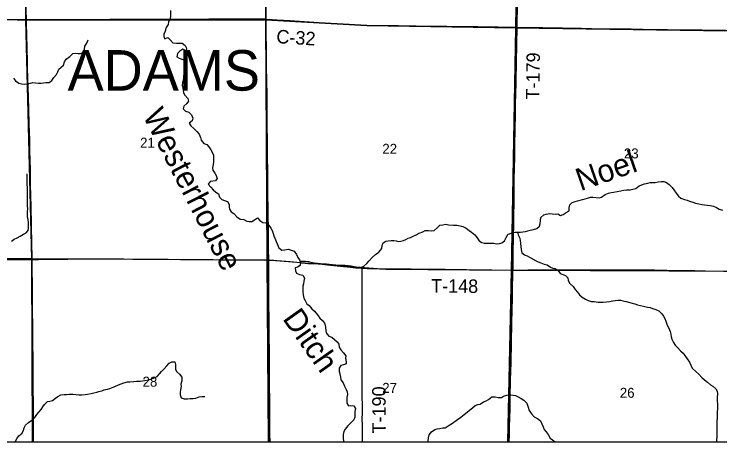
# Model space of a CAD drawing. Extents: x -8.5 to 18.7, y -20.3 to 7.
# Drawn here: x 3.11 to 9.06, y -20.26 to -16.66 of the extents above; entities that cross this region are included whole.
import ezdxf

# ---------------------------------------------------------------- set-up
doc = ezdxf.new("R2010")
doc.units = 0
for name, color, linetype in [('GM_X_Corporation', 7, 'Continuous'), ('GM_X_County_Road', 7, 'Continuous'), ('GM_X_County_Road_Text', 7, 'Continuous'), ('GM_X_Minor_River', 7, 'Continuous'), ('GM_X_Minor_River_Text', 7, 'Continuous'), ('GM_X_Section', 7, 'Continuous'), ('GM_X_Section_Text', 7, 'Continuous'), ('GM_X_State_Route', 7, 'Continuous'), ('GM_X_Township_Road', 7, 'Continuous'), ('GM_X_Township_Road_Text', 7, 'Continuous'), ('GM_X_Township_Text', 7, 'Continuous'), ('GM_X_Unincorporated_Text', 7, 'Continuous'), ('SH_Cut_Line', 7, 'Continuous')]:
    doc.layers.add(name, color=color, linetype=linetype)

msp = doc.modelspace()

# ---------------------------------------------------------------- linework, layer by layer
at = {"layer": 'GM_X_Corporation'}
msp.add_lwpolyline([(-0.9232, -20.262), (11.2623, -20.262)], dxfattribs=at)
at = {"layer": 'GM_X_County_Road'}
for points in [[(5.231, -16.7039), (5.2834, -16.707), (5.3255, -16.7098), (5.4323, -16.7162), (5.6768, -16.7311), (5.848, -16.7419), (6.028, -16.7528), (6.0764, -16.7545), (6.1671, -16.7562), (6.3486, -16.7583), (6.4966, -16.7597), (6.6271, -16.7616), (6.6744, -16.7619), (6.7564, -16.7633), (6.831, -16.7641), (6.9131, -16.7652), (7.0175, -16.7666), (7.0958, -16.7671), (7.1866, -16.7683), (7.3346, -16.7708), (7.3471, -16.771)], [(7.3471, -16.771), (7.5621, -16.7748), (7.6354, -16.7759), (7.7299, -16.7774), (7.7908, -16.7785), (7.8902, -16.7802), (7.9735, -16.7818), (8.1998, -16.7851), (8.3067, -16.7862), (8.5131, -16.7898), (8.5566, -16.7903), (8.615, -16.7911), (8.7393, -16.7925), (8.8102, -16.7933), (8.9072, -16.7947), (9.0154, -16.7963), (9.1024, -16.7972), (9.264, -16.7988), (9.3137, -16.7991), (9.3259, -16.7991)]]:
    msp.add_lwpolyline(points, dxfattribs=at)
at = {"layer": 'GM_X_Minor_River'}
for points in [[(4.4271, -16.6294), (4.4283, -16.681), (4.4206, -16.7067), (4.4114, -16.7272), (4.4067, -16.7476), (4.3907, -16.7748), (4.3807, -16.8036), (4.3715, -16.8293), (4.3698, -16.8483), (4.378, -16.8681), (4.4038, -16.8576), (4.4241, -16.8789), (4.4474, -16.9033), (4.4762, -16.9058), (4.5019, -16.9052), (4.5254, -16.9045), (4.5495, -16.9244), (4.5614, -16.9487), (4.5583, -16.9715), (4.5311, -16.9561), (4.5053, -16.9719), (4.4855, -16.9915), (4.4808, -17.0196), (4.5012, -17.0326), (4.5238, -17.0395), (4.5503, -17.048), (4.5653, -17.0694), (4.5477, -17.1019), (4.5437, -17.1292), (4.5428, -17.1542), (4.5374, -17.1814), (4.5357, -17.2095), (4.528, -17.2368), (4.5263, -17.258), (4.5307, -17.2838), (4.5329, -17.3028), (4.5365, -17.324), (4.5485, -17.3438), (4.5733, -17.3705), (4.5778, -17.394), (4.5648, -17.4144), (4.5404, -17.4371), (4.5335, -17.4575), (4.5546, -17.4781), (4.581, -17.4866), (4.6043, -17.508), (4.614, -17.5376), (4.6101, -17.5603), (4.585, -17.5799), (4.5992, -17.602), (4.6233, -17.6241), (4.6497, -17.6485), (4.6684, -17.6729)], [(3.1041, -17.2014), (3.1221, -17.2242), (3.1485, -17.2411), (3.1719, -17.2488), (3.1931, -17.252), (3.2181, -17.2491), (3.2469, -17.2416), (3.2666, -17.2372), (3.2885, -17.2396), (3.3142, -17.242), (3.3362, -17.2414), (3.3566, -17.2392), (3.3763, -17.2363), (3.4035, -17.2372), (3.4279, -17.2192), (3.4446, -17.195), (3.4667, -17.1686), (3.4767, -17.1466), (3.4874, -17.1247), (3.5072, -17.1074), (3.5262, -17.0915), (3.5339, -17.0643), (3.5485, -17.0393), (3.5789, -17.0175), (3.6032, -16.9926), (3.6267, -16.9897), (3.6486, -16.9936), (3.6683, -16.9915), (3.6933, -16.9825), (3.7033, -16.956), (3.7057, -16.9318), (3.7218, -16.9061), (3.7333, -16.8781)], [(4.6684, -17.6729), (4.6789, -17.701), (4.6855, -17.7231), (4.7073, -17.7505), (4.733, -17.759), (4.7503, -17.778), (4.766, -17.8024), (4.7788, -17.8222), (4.79, -17.8488), (4.7898, -17.8806), (4.7881, -17.9072), (4.7857, -17.9284), (4.781, -17.9557), (4.7839, -17.9754), (4.7997, -18.0005), (4.8124, -18.0203), (4.8198, -18.0454), (4.8053, -18.065), (4.7849, -18.0679), (4.7622, -18.0708), (4.7447, -18.092), (4.7657, -18.1186), (4.7852, -18.1407), (4.8101, -18.1591), (4.832, -18.1729), (4.8386, -18.2017), (4.8589, -18.2231), (4.8808, -18.23), (4.9065, -18.2393), (4.9207, -18.2651), (4.9213, -18.2841), (4.9235, -18.3038), (4.9385, -18.3251), (4.9619, -18.3389), (4.9859, -18.3663), (5.0138, -18.3885), (5.044, -18.3909), (5.0705, -18.4047), (5.0909, -18.4079), (5.1121, -18.4057), (5.1356, -18.393), (5.1607, -18.3772), (5.1802, -18.3985), (5.2051, -18.4146), (5.2338, -18.4178), (5.2541, -18.4376), (5.2729, -18.4635), (5.2826, -18.4841), (5.2908, -18.5069), (5.2982, -18.5281), (5.3057, -18.5479), (5.3161, -18.5752), (5.3281, -18.6011), (5.34, -18.6277), (5.3649, -18.6476), (5.3914, -18.6454), (5.4171, -18.6403), (5.4436, -18.6488), (5.4685, -18.658), (5.488, -18.6839), (5.4992, -18.709), (5.5135, -18.7288), (5.5209, -18.7523), (5.5192, -18.7766), (5.4957, -18.7901), (5.4767, -18.7983), (5.4789, -18.8211), (5.4886, -18.8416), (5.5142, -18.8531), (5.5414, -18.8601), (5.5549, -18.8845), (5.551, -18.9095), (5.5463, -18.9314), (5.5424, -18.9526), (5.5408, -18.9723), (5.5413, -19.0019), (5.545, -19.0232), (5.5516, -19.0528), (5.5621, -19.0718), (5.5748, -19.0992), (5.5944, -19.1137), (5.6185, -19.1411), (5.641, -19.1617), (5.6666, -19.1937), (5.6838, -19.2196), (5.7079, -19.241), (5.7237, -19.2615), (5.7311, -19.2805), (5.7325, -19.3002), (5.7361, -19.3253), (5.7398, -19.3443), (5.7608, -19.3709), (5.7865, -19.3794), (5.8083, -19.3992), (5.8324, -19.4206), (5.8459, -19.4404), (5.8481, -19.4639), (5.8615, -19.4882), (5.8849, -19.5119), (5.9029, -19.5385), (5.9027, -19.5582)], [(3.0885, -18.5732), (3.1097, -18.5567), (3.134, -18.5432), (3.1613, -18.5304), (3.1872, -18.5146), (3.2115, -18.5019), (3.229, -18.4815), (3.2298, -18.4626), (3.2315, -18.4375), (3.2309, -18.4178), (3.228, -18.3897), (3.2236, -18.37), (3.2222, -18.3442), (3.2216, -18.3237), (3.224, -18.2995), (3.2226, -18.276), (3.2228, -18.2555), (3.2214, -18.2327), (3.2217, -18.185), (3.221, -18.1637), (3.2219, -18.1387), (3.222, -18.1182), (3.2191, -18.0977), (3.2185, -18.0788), (3.2186, -18.0575), (3.2195, -18.0333), (3.2197, -18.006)], [(6.8113, -18.4387), (6.8389, -18.4373), (6.8669, -18.4435), (6.8911, -18.4497), (6.9183, -18.4635), (6.9425, -18.4833), (6.9636, -18.4979), (6.99, -18.52), (7.0104, -18.5451), (7.0277, -18.5687), (7.0511, -18.5832), (7.0723, -18.5901), (7.0951, -18.5902), (7.1208, -18.5881), (7.1511, -18.5905), (7.1746, -18.5937), (7.1988, -18.5915), (7.2178, -18.587), (7.2413, -18.5697), (7.2536, -18.5424), (7.2681, -18.5175), (7.2893, -18.507), (7.3113, -18.4987), (7.331, -18.4973), (7.353, -18.4974), (7.3749, -18.496), (7.3946, -18.4953), (7.4174, -18.4909), (7.4371, -18.4849), (7.4576, -18.4812), (7.4841, -18.4737), (7.5137, -18.4663), (7.5365, -18.4459), (7.5426, -18.4262), (7.5435, -18.3997), (7.5474, -18.3739), (7.571, -18.3497), (7.5922, -18.3453), (7.621, -18.3393), (7.6414, -18.3425), (7.6695, -18.3449), (7.6907, -18.3419), (7.7141, -18.3557), (7.7338, -18.349), (7.7597, -18.3324), (7.7855, -18.3166), (7.7856, -18.2916), (7.7902, -18.2665), (7.8115, -18.2477), (7.8373, -18.2395), (7.8562, -18.2342), (7.8782, -18.2267), (7.8972, -18.2215), (7.9199, -18.2171), (7.9389, -18.2103), (7.9655, -18.2021), (7.9859, -18.2022), (8.0374, -18.2085), (8.0579, -18.2026), (8.0898, -18.1784), (8.1171, -18.1672), (8.1383, -18.1627), (8.158, -18.1613), (8.1906, -18.1554), (8.2202, -18.1487), (8.246, -18.1427), (8.2695, -18.1391), (8.299, -18.1399), (8.321, -18.1347), (8.3468, -18.128), (8.3756, -18.1054), (8.3976, -18.0972), (8.4212, -18.0889), (8.4477, -18.083), (8.4689, -18.0785), (8.4916, -18.0779), (8.5113, -18.078), (8.5348, -18.0743), (8.5621, -18.0691), (8.5826, -18.0707), (8.6045, -18.0784), (8.6294, -18.0967), (8.6536, -18.1219), (8.6664, -18.1417), (8.686, -18.1683), (8.7063, -18.1942), (8.7267, -18.211), (8.7562, -18.2225), (8.7804, -18.2287), (8.8008, -18.2348), (8.8288, -18.2433), (8.8493, -18.2525), (8.878, -18.2579), (8.9038, -18.2626), (8.9249, -18.2673), (8.9514, -18.2697), (8.9749, -18.272), (9.0029, -18.279), (9.0264, -18.2897), (9.0483, -18.302), (9.0763, -18.312)], [(5.517, -18.7401), (5.5353, -18.7395), (5.5648, -18.7412), (5.589, -18.7444), (5.6094, -18.749), (5.6397, -18.7538), (5.6646, -18.7569), (5.6911, -18.7601), (5.7183, -18.7625), (5.7403, -18.7642), (5.7637, -18.7666), (5.7887, -18.769), (5.8212, -18.7722), (5.8787, -18.7741), (5.8998, -18.7757), (5.9225, -18.7774), (5.949, -18.7798), (5.9739, -18.7852), (6.0011, -18.7907), (6.0306, -18.7939), (6.0572, -18.7842), (6.0808, -18.7608), (6.1021, -18.7382), (6.1272, -18.7103), (6.1546, -18.6854), (6.182, -18.6658), (6.2071, -18.6356), (6.2096, -18.6076), (6.2173, -18.5872), (6.2408, -18.5714), (6.262, -18.5692), (6.2862, -18.5656), (6.3074, -18.5664), (6.3271, -18.5711), (6.3467, -18.575), (6.3687, -18.5728), (6.3891, -18.5661), (6.4089, -18.5571), (6.4294, -18.5474), (6.4491, -18.5414), (6.4711, -18.5302), (6.4961, -18.5182), (6.5227, -18.5055), (6.5523, -18.4935), (6.5713, -18.4815), (6.5985, -18.4816), (6.6227, -18.4848), (6.6477, -18.4819), (6.6743, -18.4593), (6.6964, -18.4374), (6.7214, -18.4338), (6.7479, -18.4294), (6.7683, -18.4348), (6.8113, -18.4387)], [(7.3515, -18.4974), (7.3552, -18.5179), (7.3664, -18.543), (7.3716, -18.565), (7.3768, -18.5931), (7.3775, -18.6181), (7.3804, -18.6439), (7.3864, -18.6705), (7.4105, -18.6865), (7.4317, -18.6957), (7.4529, -18.7072), (7.4756, -18.721), (7.502, -18.7355), (7.5255, -18.747), (7.5474, -18.7554), (7.5754, -18.7654), (7.6003, -18.7731), (7.6275, -18.7907), (7.6472, -18.8007), (7.6676, -18.8015), (7.6933, -18.8183), (7.7091, -18.8442), (7.7318, -18.8541), (7.756, -18.8603), (7.7734, -18.8801), (7.7778, -18.9037), (7.7921, -18.9295), (7.8193, -18.9532), (7.8366, -18.9805), (7.8547, -19.0026), (7.872, -19.0255), (7.8947, -19.0453), (7.9226, -19.0613), (7.9461, -19.0713), (7.9718, -19.079), (7.996, -19.0791), (8.0294, -19.0846), (8.0506, -19.0854), (8.0725, -19.0855), (8.1006, -19.0826), (8.1256, -19.0805), (8.1529, -19.0738), (8.1741, -19.0708), (8.1953, -19.0694), (8.2173, -19.0695), (8.2392, -19.0734), (8.2657, -19.0804), (8.296, -19.0881), (8.3172, -19.095), (8.3383, -19.1004), (8.3626, -19.1074), (8.386, -19.1135), (8.4125, -19.1197), (8.4443, -19.1267), (8.4678, -19.1321), (8.4882, -19.1398), (8.5147, -19.1483), (8.5404, -19.1598), (8.5675, -19.1842), (8.5818, -19.204), (8.5909, -19.223), (8.5999, -19.2473), (8.6118, -19.2792), (8.6261, -19.3058), (8.6366, -19.3316), (8.6434, -19.3544), (8.6448, -19.3779), (8.6493, -19.3969), (8.6635, -19.4266), (8.6793, -19.4486), (8.7005, -19.4715), (8.7238, -19.4951), (8.7472, -19.5164), (8.7653, -19.5431), (8.7789, -19.5644), (8.8, -19.591), (8.8105, -19.6153), (8.8232, -19.6404), (8.8527, -19.6701), (8.8768, -19.693), (8.9032, -19.7197), (8.9251, -19.7395), (8.9508, -19.7593), (8.9757, -19.7807), (8.9961, -19.7921), (9.0203, -19.8142), (9.033, -19.8348), (9.0345, -19.8583), (9.0328, -19.8894), (9.0335, -19.9099), (9.0341, -19.9493), (9.0347, -19.9827), (9.0331, -20.01), (9.0338, -20.0327), (9.0329, -20.0638), (9.0305, -20.0881), (9.0297, -20.1078), (9.0288, -20.1298), (9.0287, -20.1594), (9.0294, -20.1859), (9.0285, -20.217)], [(5.9027, -19.5582), (5.9071, -19.5871), (5.9077, -19.606), (5.8858, -19.6135), (5.8623, -19.6187), (5.8493, -19.6413), (5.8476, -19.6686), (5.855, -19.6899), (5.8586, -19.718), (5.8623, -19.7385), (5.8811, -19.7659), (5.8922, -19.7932), (5.908, -19.8206), (5.9162, -19.8411), (5.9168, -19.8646), (5.9136, -19.8889), (5.912, -19.9124), (5.9118, -19.9359), (5.9268, -19.9579), (5.9465, -19.9565), (5.9722, -19.9582), (5.9842, -19.9825), (5.9795, -20.0052), (5.9786, -20.034), (5.98, -20.0553), (5.9707, -20.0772), (5.9426, -20.1059), (5.9213, -20.1277), (5.8999, -20.1557), (5.8869, -20.1753), (5.8822, -20.1988), (5.8828, -20.2299), (5.8849, -20.2572), (5.8854, -20.262)], [(3.1148, -20.262), (3.1216, -20.256), (3.1353, -20.2311), (3.1491, -20.2107), (3.1764, -20.1881), (3.1887, -20.1639), (3.1949, -20.1427), (3.2064, -20.1208), (3.2307, -20.0982), (3.2588, -20.0794), (3.2847, -20.0575), (3.3022, -20.0311), (3.3175, -20.0107), (3.3381, -19.9888), (3.3518, -19.9684), (3.3663, -19.9465), (3.3899, -19.9232), (3.4096, -19.918), (3.4338, -19.9143), (3.4582, -19.8947), (3.4772, -19.8812), (3.5037, -19.8669), (3.531, -19.8625), (3.5522, -19.8619), (3.5741, -19.8613), (3.6052, -19.8614), (3.6301, -19.8623), (3.6551, -19.8647), (3.6793, -19.8649), (3.7073, -19.8628), (3.7285, -19.8606), (3.7596, -19.8547), (3.78, -19.8495), (3.805, -19.8428), (3.824, -19.8377), (3.8475, -19.831), (3.8672, -19.8242), (3.8967, -19.8176), (3.9172, -19.8116), (3.9445, -19.8027), (3.965, -19.7937), (3.99, -19.7817), (4.0105, -19.7743), (4.034, -19.766), (4.0636, -19.7579), (4.0848, -19.7557), (4.1151, -19.7529), (4.1415, -19.7515), (4.1703, -19.7501), (4.19, -19.7487), (4.2104, -19.7443), (4.2415, -19.7392), (4.2688, -19.7325), (4.2893, -19.7243), (4.3136, -19.7115), (4.3349, -19.6881), (4.3524, -19.6685), (4.3745, -19.6482), (4.3973, -19.621), (4.4171, -19.6006), (4.4376, -19.5871), (4.4633, -19.5895), (4.4678, -19.6115), (4.4684, -19.6313), (4.4698, -19.6502), (4.4772, -19.67), (4.5028, -19.6921), (4.5216, -19.7172), (4.5214, -19.7476), (4.5152, -19.7756), (4.5158, -19.7968), (4.5104, -19.8226), (4.5072, -19.8453), (4.5086, -19.8673), (4.516, -19.8901), (4.5432, -19.9008), (4.5689, -19.8995), (4.5939, -19.8973), (4.6174, -19.8982), (4.6416, -19.8931), (4.6674, -19.8826), (4.6909, -19.8789), (4.7166, -19.8791)], [(6.8019, -20.1043), (6.8459, -20.0741), (6.8718, -20.0545), (6.9006, -20.0319), (6.925, -20.0123), (6.9447, -19.9957), (6.9713, -19.9746), (6.9949, -19.9565), (7.0161, -19.9482), (7.0358, -19.9438), (7.0632, -19.9242), (7.0859, -19.9175), (7.1072, -19.9047), (7.1353, -19.8836), (7.1626, -19.8829), (7.1876, -19.8876), (7.2148, -19.8877), (7.2338, -19.8772), (7.2611, -19.8682), (7.2937, -19.8669), (7.3346, -19.8716), (7.3558, -19.8816), (7.3814, -19.8976), (7.4026, -19.9121), (7.4283, -19.9358), (7.441, -19.9699), (7.4492, -19.9988), (7.4673, -20.0269), (7.4914, -20.0513), (7.5179, -20.0659), (7.5428, -20.0849), (7.5563, -20.1093), (7.5653, -20.1366), (7.5758, -20.1571), (7.5932, -20.1762), (7.6075, -20.2005), (7.6255, -20.2309), (7.6451, -20.2462), (7.667, -20.262)], [(6.5982, -20.262), (6.5985, -20.2536), (6.6016, -20.2294), (6.6071, -20.2029), (6.6247, -20.1779), (6.6528, -20.1584), (6.6732, -20.1509), (6.6975, -20.1495), (6.7202, -20.1451), (6.7399, -20.143), (6.7665, -20.1264), (6.8019, -20.1043)], [(9.0285, -20.217), (9.0276, -20.2488), (9.027, -20.262)]]:
    msp.add_lwpolyline(points, dxfattribs=at)
at = {"layer": 'GM_X_Section'}
for points in [[(1.1578, -14.6567), (3.1911, -14.698), (3.2075, -16.709), (1.1642, -16.6782)], [(3.1911, -14.698), (5.2437, -14.6964), (5.2313, -16.7094), (3.2075, -16.709)], [(5.2437, -14.6964), (6.0431, -14.7415), (7.3681, -14.7705), (7.3365, -16.776), (6.0814, -16.7564), (5.2313, -16.7094)], [(7.3681, -14.7705), (9.3493, -14.7982), (9.3147, -16.8052), (7.3365, -16.776)], [(1.1642, -16.6782), (3.2075, -16.709), (3.2579, -18.7225), (1.1889, -18.696)], [(3.2075, -16.709), (5.2313, -16.7094), (5.2422, -18.7325), (3.2579, -18.7225)], [(5.2313, -16.7094), (6.0814, -16.7564), (7.3365, -16.776), (7.2987, -18.8185), (6.2422, -18.81), (5.2422, -18.7325)], [(7.3365, -16.776), (9.3147, -16.8052), (9.2884, -18.8288), (7.2987, -18.8185)]]:
    msp.add_lwpolyline(points, close=True, dxfattribs=at)
at = {"layer": 'GM_X_State_Route'}
for points in [[(5.231, -16.7039), (5.232, -16.581)], [(5.231, -16.7039), (5.1424, -16.7032), (5.069, -16.7039), (4.941, -16.7045), (4.8701, -16.7045), (4.7495, -16.7047), (4.6414, -16.7055), (4.4961, -16.7067), (4.3917, -16.7074), (4.2637, -16.7072), (4.1593, -16.707), (4.0425, -16.7074), (3.9853, -16.7076), (3.9169, -16.7077), (3.708, -16.7089), (3.5489, -16.7091), (3.4345, -16.7091), (3.4022, -16.7089), (3.3288, -16.7098), (3.2125, -16.7109), (3.2033, -16.7109), (3.1349, -16.7108), (2.9993, -16.71)], [(5.2466, -17.9834), (5.2449, -17.8611), (5.2443, -17.8126), (5.2436, -17.7244), (5.2426, -17.6038), (5.242, -17.5491), (5.2418, -17.487), (5.2401, -17.3415), (5.237, -17.1091), (5.2348, -16.9462), (5.2325, -16.8294), (5.2318, -16.7299), (5.231, -16.7039)], [(5.2558, -18.9631), (5.2551, -18.8928), (5.2542, -18.7449), (5.2541, -18.7311), (5.2533, -18.6318), (5.2531, -18.5622), (5.2517, -18.4739), (5.2499, -18.3459), (5.2482, -18.1358), (5.2468, -17.9954), (5.2466, -17.9834)], [(5.2661, -20.262), (5.2652, -20.198), (5.2641, -20.1085), (5.2637, -20.0352), (5.2628, -19.988), (5.2628, -19.9407), (5.2628, -19.8686), (5.2624, -19.8313), (5.2621, -19.7182), (5.2617, -19.6436), (5.2616, -19.5081), (5.2595, -19.3764), (5.2575, -19.2533), (5.2568, -19.0743), (5.2559, -18.9711), (5.2558, -18.9631)]]:
    msp.add_lwpolyline(points, dxfattribs=at)
at = {"layer": 'GM_X_Township_Road'}
for points in [[(3.2125, -16.7109), (3.2125, -16.702), (3.2117, -16.6325), (3.2117, -16.6111), (3.2109, -16.5548), (3.2098, -16.472), (3.2086, -16.4123), (3.2081, -16.3415), (3.2073, -16.2581), (3.2062, -16.1711), (3.2047, -16.007), (3.2039, -15.9448), (3.2036, -15.8727), (3.2032, -15.8392), (3.203, -15.8118), (3.2023, -15.7671), (3.2008, -15.7212), (3.1999, -15.71), (3.199, -15.7039), (3.1971, -15.6911)], [(7.3471, -16.771), (7.3482, -16.6955), (7.3491, -16.6421), (7.3504, -16.5612), (7.3523, -16.468), (7.3541, -16.3922), (7.355, -16.3649), (7.3548, -16.3376), (7.3552, -16.2911)], [(3.2615, -18.726), (3.2613, -18.707), (3.2589, -18.5889), (3.2559, -18.4422), (3.2521, -18.2681), (3.2511, -18.2035), (3.2487, -18.0866), (3.2462, -17.9685), (3.2431, -17.8119), (3.2407, -17.7212), (3.2391, -17.6565), (3.2365, -17.5844), (3.2336, -17.4576), (3.2306, -17.362), (3.2279, -17.2775), (3.2258, -17.1967), (3.2235, -17.1159), (3.222, -17.045), (3.2194, -16.9643), (3.2181, -16.922), (3.2168, -16.8599), (3.2153, -16.8065), (3.2143, -16.7743), (3.2136, -16.7533), (3.2126, -16.7225), (3.2125, -16.7109)], [(7.3123, -18.8162), (7.3128, -18.8022), (7.3137, -18.7712), (7.3153, -18.6729), (7.3166, -18.5396), (7.3187, -18.433), (7.3199, -18.3472), (7.321, -18.259), (7.3225, -18.218), (7.3229, -18.1931), (7.3227, -18.1621), (7.3235, -18.0725), (7.326, -17.9359), (7.327, -17.8911), (7.3277, -17.8166), (7.3284, -17.8121), (7.3281, -17.7523), (7.3284, -17.7424), (7.3293, -17.7175), (7.3307, -17.6752), (7.3307, -17.643), (7.331, -17.6345), (7.3309, -17.6309), (7.3313, -17.6175), (7.3313, -17.6103), (7.3332, -17.5259), (7.3346, -17.4226), (7.3383, -17.24), (7.3393, -17.1989), (7.3413, -17.087), (7.3422, -17.0286), (7.3435, -16.9565), (7.345, -16.877), (7.3465, -16.8099), (7.3471, -16.771)], [(3.0353, -18.7262), (3.1236, -18.7262), (3.2355, -18.7261), (3.2615, -18.726)], [(3.2615, -18.726), (3.3151, -18.726), (3.3797, -18.7251), (3.4394, -18.7246), (3.5612, -18.7234), (3.7117, -18.7225), (4.0337, -18.7223), (4.1095, -18.7227), (4.1854, -18.7235), (4.2811, -18.7242), (4.3433, -18.7245), (4.4079, -18.7251), (4.5124, -18.7256), (4.5273, -18.7258), (4.5932, -18.7263), (4.6877, -18.7273), (4.7846, -18.7275), (4.8605, -18.7284), (4.991, -18.7291), (5.083, -18.7301), (5.1265, -18.7305), (5.1529, -18.731), (5.1748, -18.7304), (5.1997, -18.731), (5.2227, -18.7313), (5.2367, -18.731), (5.2541, -18.7311)], [(3.2723, -20.262), (3.2721, -20.225), (3.2719, -20.1628), (3.2718, -20.0969), (3.2717, -20.0397), (3.2716, -19.9614), (3.2715, -19.9055), (3.271, -19.8471), (3.2711, -19.7737), (3.2706, -19.7029), (3.2689, -19.5723), (3.2679, -19.4268), (3.2667, -19.2751), (3.2656, -19.1769), (3.2653, -19.0998), (3.2631, -18.9469), (3.2627, -18.8052), (3.2615, -18.726)], [(5.2541, -18.7311), (5.2721, -18.7315), (5.2969, -18.733), (5.3266, -18.7352), (5.3612, -18.7378), (5.4356, -18.7439), (5.4913, -18.7492), (5.5345, -18.7541), (5.5629, -18.7575), (5.5839, -18.7592), (5.5889, -18.7594), (5.5976, -18.7599), (5.6075, -18.7602), (5.6187, -18.7601), (5.6461, -18.7607), (5.6832, -18.7639), (5.7511, -18.7716), (5.8834, -18.7862), (5.944, -18.7927), (5.9885, -18.7968), (6.0344, -18.8), (6.041, -18.8003)], [(6.041, -18.8003), (6.0829, -18.8023), (6.1201, -18.8034), (6.1873, -18.8043), (6.242, -18.8042), (6.3464, -18.8058), (6.4545, -18.8067), (6.5329, -18.8075), (6.7417, -18.8096), (6.9208, -18.8118), (7.07, -18.8136), (7.1346, -18.8139), (7.3099, -18.8163), (7.3123, -18.8162)], [(6.0415, -19.4169), (6.0413, -19.3844), (6.0414, -19.3607), (6.0416, -19.3284), (6.0414, -19.2128), (6.0419, -19.0449), (6.0417, -18.9293), (6.0417, -18.8622), (6.0416, -18.8286), (6.0413, -18.8137), (6.041, -18.8003)], [(7.2806, -20.262), (7.2821, -20.2029), (7.2839, -20.1321), (7.2853, -20.0624), (7.2873, -19.9816), (7.2893, -19.8896), (7.2922, -19.743), (7.2958, -19.5938), (7.2995, -19.4222), (7.3024, -19.2668), (7.3051, -19.1487), (7.307, -19.0567), (7.3083, -18.9858), (7.3094, -18.9349), (7.3106, -18.8802), (7.3123, -18.8162)], [(7.3123, -18.8162), (7.3484, -18.8159), (7.4367, -18.8151), (7.5162, -18.8146), (7.561, -18.8146), (7.6505, -18.8135), (7.6803, -18.8135), (7.7885, -18.8135), (7.8195, -18.813), (7.8444, -18.813), (7.8668, -18.8132), (7.9699, -18.8134), (8.0905, -18.8131), (8.2385, -18.8132), (8.3305, -18.8135), (8.5033, -18.815), (8.609, -18.8168), (8.8439, -18.8203), (8.9334, -18.8217), (9.0851, -18.8237), (9.1647, -18.8251), (9.2405, -18.8263), (9.2865, -18.827), (9.3003, -18.8271)], [(6.0421, -19.4772), (6.0421, -19.4614), (6.0416, -19.4291), (6.0415, -19.4169)], [(6.0404, -20.262), (6.0406, -20.262), (6.0429, -20.2591), (6.0438, -20.2568), (6.0445, -20.2532), (6.0447, -20.227), (6.044, -20.1947), (6.0433, -20.1214), (6.0427, -20.0691), (6.0436, -20.0195), (6.0434, -19.9846), (6.0432, -19.9387), (6.0429, -19.8965), (6.0428, -19.853), (6.0425, -19.7684), (6.0424, -19.7237), (6.0424, -19.6703), (6.0425, -19.6342), (6.0424, -19.582), (6.0422, -19.5235), (6.042, -19.5049), (6.0421, -19.4772)], [(5.8502, -20.262), (5.8504, -20.2619), (5.854, -20.2612), (5.8603, -20.261), (5.8728, -20.2612), (5.8802, -20.2609)]]:
    msp.add_lwpolyline(points, dxfattribs=at)
at = {"layer": 'GM_X_Unincorporated_Text'}
for points in [[(1.2233, -20.262), (3.2635, -20.262), (3.2579, -18.7225), (1.1889, -18.696)], [(3.2635, -20.262), (5.2534, -20.262), (5.2422, -18.7325), (3.2579, -18.7225)], [(5.2534, -20.262), (7.2687, -20.262), (7.2987, -18.8185), (6.2422, -18.81), (5.2422, -18.7325)], [(7.2687, -20.262), (9.2701, -20.262), (9.2884, -18.8288), (7.2987, -18.8185)]]:
    msp.add_lwpolyline(points, close=True, dxfattribs=at)
at = {"layer": 'SH_Cut_Line'}
msp.add_lwpolyline([(-8.4587, -10.6981), (-8.4587, -20.262), (18.7413, -20.262), (18.7413, -10.9039)], dxfattribs=at)

# ---------------------------------------------------------------- texts
at = {"layer": 'GM_X_County_Road_Text'}
msp.add_text('C-32', height=0.11364, rotation=356.23092, dxfattribs=at).set_placement((5.316, -16.9047))
at = {"layer": 'GM_X_Minor_River_Text'}
for s, height, rotation, p in [('Westerhouse', 0.189475, 297.21107, (4.1896, -17.5136)), ('Noel', 0.18949, 19.21107, (7.8812, -18.1522)), ('Ditch', 0.18944, 305.21387, (5.3653, -19.2249))]:
    msp.add_text(s, height=height, rotation=rotation, dxfattribs=at).set_placement(p)
at = {"layer": 'GM_X_Section_Text'}
for s, p in [('21', (4.1707, -17.7853)), ('22', (6.2115, -17.837)), ('23', (8.2465, -17.8759)), ('28', (4.1915, -19.7976)), ('27', (6.2107, -19.8493)), ('26', (8.2123, -19.8909))]:
    msp.add_text(s, height=0.08371, rotation=0.00001, dxfattribs=at).set_placement(p)
at = {"layer": 'GM_X_Township_Road_Text'}
for s, rotation, p in [('T-179', 89.15849, (7.5346, -17.3814)), ('T-148', 359.43955, (6.6218, -19.0049)), ('T-190', 90.28012, (6.2412, -20.1916))]:
    msp.add_text(s, height=0.11364, rotation=rotation, dxfattribs=at).set_placement(p)
at = {"layer": 'GM_X_Township_Text'}
msp.add_text('ADAMS', height=0.34091, rotation=0.00001, dxfattribs=at).set_placement((3.5598, -17.3053))

doc.saveas('drawing.dxf')
